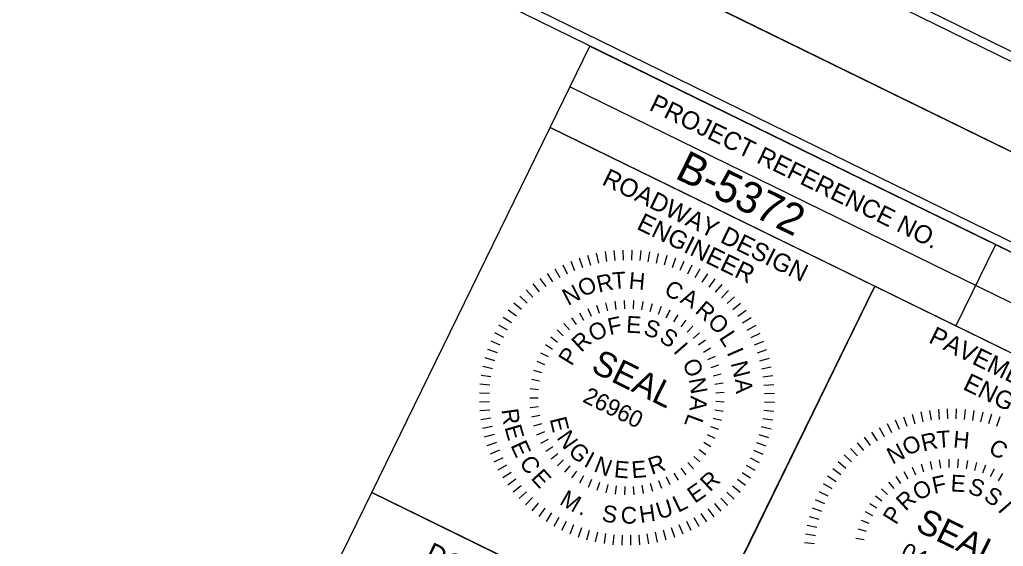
# Model space of a CAD drawing. Extents: x 1518247 to 1523638, y 635234 to 639927.
# Drawn here: x 1522074.1 to 1522346.5, y 638133.1 to 638278.9 of the extents above; entities that cross this region are included whole.
import ezdxf

# ---------------------------------------------------------------- set-up
doc = ezdxf.new("R2010")
doc.units = 0
for name, color, linetype in [('Default', 7, 'Continuous'), ('DTM TIN Hull White', 7, 'Continuous'), ('Prop Dimension Text', 7, 'Continuous'), ('Sheet Cutting Line CELL', 7, 'Continuous'), ('Sheet Plot Border Inside CELL', 7, 'Continuous'), ('Sheet Plot Border Outside CELL', 7, 'Continuous'), ('Sheet Sticker Exception Certification CELL', 7, 'Continuous'), ('Sheet Typical CELL', 7, 'Continuous')]:
    doc.layers.add(name, color=color, linetype=linetype)

msp = doc.modelspace()

# ---------------------------------------------------------------- linework, layer by layer
at = {"layer": 'Default'}
for points in [[(1522438.02, 638198.63), (1520925.25, 638938.49), (1521408.53, 639926.64), (1522921.3, 639186.78)], [(1520441.97, 637950.34), (1521954.73, 637210.48), (1522438.02, 638198.63), (1520925.25, 638938.49)]]:
    msp.add_lwpolyline(points, close=True, dxfattribs=at)
at = {"layer": 'DTM TIN Hull White'}
for p, q in [((1522233.81, 638214.21), (1522234.39, 638211.49)), ((1522236.24, 638214.65), (1522236.65, 638211.9)), ((1522238.69, 638214.94), (1522238.94, 638212.17)), ((1522241.16, 638215.09), (1522241.23, 638212.3)), ((1522243.63, 638215.08), (1522243.53, 638212.29)), ((1522246.09, 638214.93), (1522245.83, 638212.15)), ((1522248.54, 638214.62), (1522248.11, 638211.86)), ((1522250.97, 638214.17), (1522250.38, 638211.45)), ((1522226.74, 638212.03), (1522227.8, 638209.46)), ((1522229.05, 638212.9), (1522229.95, 638210.26)), ((1522231.41, 638213.63), (1522232.15, 638210.94)), ((1522253.37, 638213.57), (1522252.61, 638210.89)), ((1522255.72, 638212.83), (1522254.8, 638210.2)), ((1522258.02, 638211.95), (1522256.95, 638209.38)), ((1522220.18, 638208.61), (1522221.69, 638206.27)), ((1522222.3, 638209.88), (1522223.66, 638207.45)), ((1522224.49, 638211.02), (1522225.7, 638208.52)), ((1522260.28, 638210.93), (1522259.05, 638208.43)), ((1522262.46, 638209.77), (1522261.09, 638207.35)), ((1522264.57, 638208.49), (1522263.05, 638206.16)), ((1522216.2, 638205.69), (1522217.98, 638203.55)), ((1522218.14, 638207.21), (1522219.79, 638204.96)), ((1522266.6, 638207.08), (1522264.94, 638204.85)), ((1522214.34, 638204.06), (1522216.25, 638202.03)), ((1522268.53, 638205.56), (1522266.75, 638203.42)), ((1522270.38, 638203.91), (1522268.47, 638201.89)), ((1522210.95, 638200.48), (1522213.09, 638198.69)), ((1522212.59, 638202.33), (1522214.62, 638200.41)), ((1522236.38, 638200.51), (1522236.89, 638198.24)), ((1522238.95, 638200.96), (1522239.23, 638198.65)), ((1522241.54, 638201.16), (1522241.6, 638198.84)), ((1522244.14, 638201.1), (1522243.98, 638198.79)), ((1522246.73, 638200.8), (1522246.35, 638198.51)), ((1522249.27, 638200.24), (1522248.67, 638198)), ((1522272.12, 638202.16), (1522270.08, 638200.26)), ((1522273.75, 638200.31), (1522271.61, 638198.53)), ((1522209.42, 638198.54), (1522211.66, 638196.88)), ((1522229.11, 638197.73), (1522230.24, 638195.7)), ((1522231.44, 638198.89), (1522232.38, 638196.76)), ((1522233.87, 638199.82), (1522234.6, 638197.61)), ((1522251.75, 638199.45), (1522250.93, 638197.27)), ((1522254.14, 638198.41), (1522253.12, 638196.33)), ((1522253.12, 638196.33), (1522254.14, 638198.41)), ((1522275.27, 638198.36), (1522273.02, 638196.72)), ((1522208.02, 638196.51), (1522210.35, 638194.99)), ((1522224.84, 638194.76), (1522226.34, 638192.99)), ((1522226.91, 638196.35), (1522228.23, 638194.44)), ((1522256.42, 638197.16), (1522255.2, 638195.18)), ((1522258.57, 638195.69), (1522257.17, 638193.84)), ((1522276.67, 638196.33), (1522274.32, 638194.82)), ((1522205.58, 638192.22), (1522208.08, 638190.99)), ((1522206.74, 638194.4), (1522209.16, 638193.03)), ((1522222.94, 638192.98), (1522224.61, 638191.36)), ((1522260.56, 638194.02), (1522258.99, 638192.31)), ((1522262.39, 638192.16), (1522260.66, 638190.61)), ((1522277.94, 638194.21), (1522275.51, 638192.85)), ((1522204.56, 638189.97), (1522207.13, 638188.89)), ((1522221.22, 638191.03), (1522223.04, 638189.58)), ((1522264.02, 638190.13), (1522262.15, 638188.76)), ((1522279.08, 638192.02), (1522276.57, 638190.81)), ((1522280.09, 638189.77), (1522277.51, 638188.71)), ((1522203.68, 638187.66), (1522206.31, 638186.75)), ((1522218.39, 638186.67), (1522220.44, 638185.59)), ((1522219.7, 638188.91), (1522221.64, 638187.65)), ((1522265.46, 638187.96), (1522263.46, 638186.77)), ((1522280.96, 638187.45), (1522278.32, 638186.55)), ((1522202.94, 638185.31), (1522205.62, 638184.55)), ((1522217.3, 638184.3), (1522219.45, 638183.43)), ((1522266.68, 638185.66), (1522264.57, 638184.67)), ((1522281.69, 638185.1), (1522279, 638184.36)), ((1522202.34, 638182.91), (1522205.06, 638182.32)), ((1522216.44, 638181.84), (1522218.67, 638181.19)), ((1522267.66, 638183.25), (1522265.48, 638182.47)), ((1522282.27, 638182.7), (1522279.55, 638182.12)), ((1522201.89, 638180.48), (1522204.64, 638180.05)), ((1522215.83, 638179.31), (1522218.1, 638178.87)), ((1522268.42, 638180.76), (1522266.17, 638180.2)), ((1522282.71, 638180.27), (1522279.96, 638179.86)), ((1522201.58, 638178.04), (1522204.36, 638177.78)), ((1522215.46, 638176.73), (1522217.77, 638176.52)), ((1522268.93, 638178.21), (1522266.63, 638177.86)), ((1522283, 638177.82), (1522280.23, 638177.57)), ((1522201.42, 638173.1), (1522204.21, 638173.18)), ((1522201.43, 638175.57), (1522204.21, 638175.48)), ((1522215.35, 638174.14), (1522217.67, 638174.15)), ((1522269.19, 638175.62), (1522266.87, 638175.49)), ((1522269.2, 638173.01), (1522266.88, 638173.12)), ((1522283.13, 638172.88), (1522280.35, 638172.97)), ((1522283.14, 638175.35), (1522280.36, 638175.27)), ((1522201.56, 638170.63), (1522204.34, 638170.88)), ((1522215.48, 638171.54), (1522217.79, 638171.77)), ((1522268.95, 638170.42), (1522266.65, 638170.75)), ((1522282.98, 638170.42), (1522280.21, 638170.67)), ((1522323.67, 638170.27), (1522324.24, 638167.54)), ((1522326.09, 638170.71), (1522326.51, 638167.95)), ((1522328.55, 638171), (1522328.79, 638168.22)), ((1522331.01, 638171.14), (1522331.09, 638168.35)), ((1522333.48, 638171.13), (1522333.39, 638168.35)), ((1522335.95, 638170.98), (1522335.69, 638168.2)), ((1522338.39, 638170.68), (1522337.97, 638167.92)), ((1522201.86, 638168.18), (1522204.61, 638168.6)), ((1522215.86, 638168.96), (1522218.14, 638169.41)), ((1522268.46, 638167.87), (1522266.21, 638168.42)), ((1522282.68, 638167.97), (1522279.92, 638168.4)), ((1522316.6, 638168.09), (1522317.66, 638165.51)), ((1522318.91, 638168.95), (1522319.81, 638166.32)), ((1522321.27, 638169.68), (1522322.01, 638167)), ((1522340.83, 638170.22), (1522340.23, 638167.5)), ((1522343.22, 638169.63), (1522342.46, 638166.94)), ((1522345.57, 638168.88), (1522344.66, 638166.25)), ((1522202.3, 638165.76), (1522205.02, 638166.33)), ((1522216.5, 638166.44), (1522218.71, 638167.11)), ((1522217.36, 638163.98), (1522219.51, 638164.87)), ((1522267.73, 638165.37), (1522265.54, 638166.13)), ((1522282.23, 638165.54), (1522279.5, 638166.13)), ((1522312.15, 638165.94), (1522313.51, 638163.51)), ((1522314.34, 638167.08), (1522315.55, 638164.57)), ((1522202.88, 638163.35), (1522205.57, 638164.1)), ((1522218.47, 638161.63), (1522220.52, 638162.71)), ((1522266.75, 638162.95), (1522264.64, 638163.92)), ((1522281.63, 638163.14), (1522278.95, 638163.9)), ((1522308, 638163.27), (1522309.65, 638161.02)), ((1522310.04, 638164.67), (1522311.54, 638162.32)), ((1522203.61, 638161), (1522206.24, 638161.9)), ((1522204.48, 638158.69), (1522207.05, 638159.74)), ((1522219.8, 638159.39), (1522221.74, 638160.67)), ((1522262.3, 638159.89), (1522264.18, 638158.53)), ((1522265.55, 638160.65), (1522263.55, 638161.81)), ((1522280, 638158.48), (1522277.44, 638159.56)), ((1522280.89, 638160.79), (1522278.26, 638161.71)), ((1522304.2, 638160.12), (1522306.1, 638158.08)), ((1522306.05, 638161.75), (1522307.83, 638159.61)), ((1522205.49, 638156.43), (1522207.99, 638157.64)), ((1522221.34, 638157.29), (1522223.14, 638158.75)), ((1522223.07, 638155.34), (1522224.73, 638156.97)), ((1522262.51, 638156.43), (1522260.77, 638157.96)), ((1522278.99, 638156.23), (1522276.48, 638157.46)), ((1522302.45, 638158.38), (1522304.48, 638156.46)), ((1522328.8, 638157.01), (1522329.09, 638154.71)), ((1522331.4, 638157.21), (1522331.46, 638154.89)), ((1522334, 638157.16), (1522333.84, 638154.84)), ((1522336.59, 638156.85), (1522336.2, 638154.56)), ((1522206.63, 638154.24), (1522209.06, 638155.6)), ((1522226.46, 638155.37), (1522224.97, 638153.59)), ((1522227.06, 638152), (1522228.37, 638153.92)), ((1522258.71, 638152.88), (1522257.3, 638154.72)), ((1522260.69, 638154.56), (1522259.11, 638156.25)), ((1522277.83, 638154.05), (1522275.41, 638155.42)), ((1522299.28, 638154.59), (1522301.52, 638152.94)), ((1522300.8, 638156.53), (1522302.94, 638154.75)), ((1522321.3, 638154.94), (1522322.23, 638152.82)), ((1522323.73, 638155.87), (1522324.45, 638153.66)), ((1522326.23, 638156.57), (1522326.74, 638154.3)), ((1522339.13, 638156.3), (1522338.52, 638154.06)), ((1522341.6, 638155.5), (1522340.79, 638153.33)), ((1522344, 638154.47), (1522342.97, 638152.39)), ((1522342.97, 638152.39), (1522344, 638154.47)), ((1522207.9, 638152.13), (1522210.24, 638153.63)), ((1522209.29, 638150.09), (1522211.54, 638151.73)), ((1522229.27, 638150.64), (1522230.39, 638152.67)), ((1522231.61, 638149.49), (1522232.53, 638151.62)), ((1522251.92, 638149.07), (1522251.09, 638151.23)), ((1522254.3, 638150.11), (1522253.27, 638152.19)), ((1522256.58, 638151.39), (1522255.34, 638153.35)), ((1522275.14, 638149.91), (1522272.9, 638151.57)), ((1522276.55, 638151.94), (1522274.21, 638153.46)), ((1522297.87, 638152.56), (1522300.21, 638151.05)), ((1522316.76, 638152.4), (1522318.08, 638150.49)), ((1522318.97, 638153.78), (1522320.1, 638151.75)), ((1522346.28, 638153.21), (1522345.06, 638151.24)), ((1522210.82, 638148.14), (1522212.96, 638149.92)), ((1522234.04, 638148.58), (1522234.75, 638150.79)), ((1522236.56, 638147.9), (1522237.05, 638150.17)), ((1522239.12, 638147.47), (1522239.4, 638149.78)), ((1522241.72, 638147.29), (1522241.77, 638149.62)), ((1522244.33, 638147.36), (1522244.15, 638149.68)), ((1522246.91, 638147.69), (1522246.51, 638149.97)), ((1522249.45, 638148.26), (1522248.83, 638150.49)), ((1522273.62, 638147.97), (1522271.48, 638149.76)), ((1522296.59, 638150.46), (1522299.01, 638149.08)), ((1522312.8, 638149.03), (1522314.47, 638147.42)), ((1522314.69, 638150.81), (1522316.2, 638149.04)), ((1522212.44, 638146.29), (1522214.48, 638148.19)), ((1522214.18, 638144.54), (1522216.1, 638146.56)), ((1522270.22, 638144.39), (1522268.32, 638146.42)), ((1522271.97, 638146.13), (1522269.94, 638148.04)), ((1522294.42, 638146.02), (1522296.99, 638144.95)), ((1522295.44, 638148.27), (1522297.94, 638147.05)), ((1522311.08, 638147.08), (1522312.89, 638145.63)), ((1522216.03, 638142.89), (1522217.82, 638145.03)), ((1522217.97, 638141.37), (1522219.62, 638143.61)), ((1522266.42, 638141.24), (1522264.77, 638143.49)), ((1522268.37, 638142.76), (1522266.59, 638144.9)), ((1522293.54, 638143.72), (1522296.16, 638142.8)), ((1522309.55, 638144.97), (1522311.5, 638143.71)), ((1522220, 638139.96), (1522221.51, 638142.3)), ((1522222.11, 638138.68), (1522223.48, 638141.1)), ((1522262.27, 638138.57), (1522260.91, 638141)), ((1522264.38, 638139.84), (1522262.88, 638142.18)), ((1522292.79, 638141.36), (1522295.47, 638140.61)), ((1522307.15, 638140.36), (1522309.3, 638139.49)), ((1522308.24, 638142.72), (1522310.3, 638141.65)), ((1522224.29, 638137.52), (1522225.52, 638140.03)), ((1522226.54, 638136.5), (1522227.61, 638139.07)), ((1522228.85, 638135.62), (1522229.76, 638138.25)), ((1522231.2, 638134.88), (1522231.96, 638137.56)), ((1522255.51, 638135.55), (1522254.61, 638138.19)), ((1522257.82, 638136.42), (1522256.76, 638139)), ((1522260.08, 638137.43), (1522258.87, 638139.93)), ((1522292.2, 638138.97), (1522294.92, 638138.37)), ((1522306.3, 638137.9), (1522308.52, 638137.24)), ((1522233.59, 638134.28), (1522234.19, 638137)), ((1522236.03, 638133.83), (1522236.45, 638136.59)), ((1522238.47, 638133.53), (1522238.73, 638136.3)), ((1522240.94, 638133.38), (1522241.03, 638136.16)), ((1522243.41, 638133.36), (1522243.33, 638136.15)), ((1522245.87, 638133.51), (1522245.63, 638136.28)), ((1522248.33, 638133.8), (1522247.91, 638136.55)), ((1522250.75, 638134.24), (1522250.18, 638136.96)), ((1522253.16, 638134.82), (1522252.41, 638137.51)), ((1522291.74, 638136.54), (1522294.5, 638136.11)), ((1522305.68, 638135.37), (1522307.96, 638134.93)), ((1522291.44, 638134.09), (1522294.21, 638133.83))]:
    msp.add_line(p, q, dxfattribs=at)
at = {"layer": 'Sheet Cutting Line CELL'}
for p, q in [((1520925.25, 638938.49), (1522438.02, 638198.63)), ((1522438.02, 638198.63), (1520925.25, 638938.49))]:
    msp.add_line(p, q, dxfattribs=at)
at = {"layer": 'Sheet Plot Border Inside CELL'}
for points in [[(1522907.39, 639168.59), (1521410.35, 639900.76), (1520946.79, 638952.95), (1522443.84, 638220.77)], [(1522424.11, 638180.44), (1520927.06, 638912.61), (1520463.51, 637964.8), (1521960.55, 637232.62)]]:
    msp.add_lwpolyline(points, close=True, dxfattribs=at)
at = {"layer": 'Sheet Plot Border Outside CELL'}
for points in [[(1522921.3, 639186.78), (1521408.53, 639926.64), (1520925.25, 638938.49), (1522438.02, 638198.63)], [(1522438.02, 638198.63), (1520925.25, 638938.49), (1520441.97, 637950.34), (1521954.73, 637210.48)]]:
    msp.add_lwpolyline(points, close=True, dxfattribs=at)
at = {"layer": 'Sheet Sticker Exception Certification CELL'}
for p, q in [((1522161.3, 638126.86), (1522171.62, 638147.97)), ((1522171.62, 638147.97), (1522351.32, 638060.08))]:
    msp.add_line(p, q, dxfattribs=at)
at = {"layer": 'Sheet Typical CELL'}
for p, q in [((1522226.54, 638260.26), (1522406.25, 638172.37)), ((1522344.36, 638216.55), (1522333.38, 638194.09)), ((1522310.92, 638205.07), (1522261.52, 638104.06))]:
    msp.add_line(p, q, dxfattribs=at)
for points in [[(1522895.04, 639171.79), (1521547.57, 639830.81), (1521086.25, 638887.58), (1522433.73, 638228.56)], [(1522411.76, 638183.64), (1521064.29, 638842.66), (1520602.97, 637899.43), (1521950.45, 637240.41)], [(1522232.05, 638271.53), (1522411.76, 638183.64), (1522400.76, 638161.14), (1522221.05, 638249.03)], [(1522221.05, 638249.03), (1522310.92, 638205.07), (1522261.5, 638104.01), (1522171.62, 638147.97)], [(1522310.92, 638205.07), (1522400.76, 638161.14), (1522351.33, 638060.08), (1522261.5, 638104.01)]]:
    msp.add_lwpolyline(points, close=True, dxfattribs=at)

# ---------------------------------------------------------------- texts
at = {"layer": 'DTM TIN Hull White'}
for s, height, rotation, p in [('R', 4.64, 12.5453, (1522234.47, 638203.27)), ('T', 4.64, 4.3843, (1522238.41, 638204.23)), ('H', 4.64, 354.9524, (1522242.66, 638204.4)), ('O', 4.64, 25.602, (1522230.07, 638201.94)), ('C', 4.64, 331.2417, (1522252.26, 638203.01)), ('N', 4.64, 27.5614, (1522225.96, 638199.6)), ('A', 4.64, 331.2417, (1522256.77, 638200.7)), ('R', 4.64, 319.2324, (1522260.88, 638197.92)), ('O', 4.64, 27.4216, (1522233.09, 638189.51)), ('F', 4.64, 12.1253, (1522237.51, 638191.52)), ('E', 4.64, 356.8291, (1522242, 638192.24)), ('S', 4.64, 341.5328, (1522246.61, 638191.75)), ('O', 4.64, 316.1756, (1522264.33, 638194.74)), ('R', 4.64, 42.7178, (1522229.61, 638186.58)), ('S', 4.64, 326.2366, (1522250.94, 638190.06)), ('L', 4.64, 303.0393, (1522267.66, 638190.81)), ('I', 4.64, 310.9403, (1522254.93, 638186.99)), ('P', 4.64, 58.0141, (1522226.95, 638182.76)), ('SEAL', 6.965, 333.8847, (1522232, 638181.6)), ('I', 4.64, 293.4638, (1522269.84, 638186.74)), ('O', 4.64, 295.6441, (1522257.49, 638183.72)), ('N', 4.64, 284.1693, (1522270.96, 638183.75)), ('N', 4.64, 280.3478, (1522259.34, 638179.35)), ('A', 4.64, 274.4018, (1522272.2, 638179.33)), ('26960', 4.64, 333.8847, (1522229.75, 638173.19)), ('A', 4.64, 265.0516, (1522259.95, 638174.82)), ('R', 4.64, 277.8197, (1522207.53, 638170.9)), ('E', 4.64, 283.9548, (1522220.86, 638168.31)), ('L', 4.64, 249.7554, (1522259.28, 638170.04)), ('E', 4.64, 285.8915, (1522208.35, 638166.03)), ('N', 4.64, 304.8099, (1522222.66, 638163.13)), ('T', 4.64, 4.3843, (1522328.27, 638160.28)), ('H', 4.64, 354.9524, (1522332.51, 638160.45)), ('E', 4.64, 294.5343, (1522209.97, 638161.03)), ('O', 4.64, 25.602, (1522319.93, 638158)), ('R', 4.64, 12.5453, (1522324.32, 638159.32)), ('C', 4.64, 331.2417, (1522342.11, 638159.06)), ('G', 4.64, 313.5761, (1522225.78, 638159.17)), ('N', 4.64, 27.5614, (1522315.81, 638155.65)), ('C', 4.64, 303.2069, (1522212.32, 638156.32)), ('I', 4.64, 331.6709, (1522230.09, 638155.41)), ('N', 4.64, 339.3006, (1522232.85, 638153.88)), ('E', 4.64, 354.6926, (1522238.58, 638152.22)), ('E', 4.64, 4.6785, (1522243.73, 638151.91)), ('R', 4.64, 18.4496, (1522249.12, 638152.87)), ('E', 4.64, 312.1794, (1522215.49, 638151.85)), ('R', 4.64, 43.5571, (1522265.28, 638147.97)), ('F', 4.64, 12.1253, (1522327.36, 638147.57)), ('E', 4.64, 356.8291, (1522331.85, 638148.29)), ('S', 4.64, 341.5328, (1522336.47, 638147.81)), ('M', 4.64, 329.9747, (1522223.34, 638144.89)), ('E', 4.64, 34.8844, (1522261.08, 638144.82)), ('O', 4.64, 27.4216, (1522322.94, 638145.57)), ('S', 4.64, 326.2366, (1522340.8, 638146.11)), ('U', 4.64, 17.2091, (1522251.2, 638140.48)), ('L', 4.64, 26.0918, (1522256.44, 638142.33)), ('R', 4.64, 42.7178, (1522319.46, 638142.64)), ('S', 4.64, 350.5013, (1522235.12, 638140.07)), ('C', 4.64, 359.5039, (1522240.56, 638139.37)), ('H', 4.64, 8.3265, (1522246.03, 638139.53)), ('P', 4.64, 58.0141, (1522316.81, 638138.81)), ('SEAL', 6.965, 333.8847, (1522321.85, 638137.65)), ('I', 4.64, 310.9403, (1522344.79, 638143.04)), ('.', 4.64, 337.717, (1522228.72, 638142.1)), ('044590', 4.64, 333.8847, (1522317.77, 638130.14))]:
    msp.add_text(s, height=height, rotation=rotation, dxfattribs=at).set_placement(p)
at = {"layer": 'Prop Dimension Text'}
msp.add_text('B-5372', height=8.643, rotation=333.8962, dxfattribs=at).set_placement((1522255.3, 638235.13))
at = {"layer": 'Sheet Sticker Exception Certification CELL'}
msp.add_text('DOCUMENT NOT CONSIDERED FINAL', height=5.5, rotation=333.9377, dxfattribs=at).set_placement((1522186, 638129.42))
at = {"layer": 'Sheet Typical CELL'}
for s, height, p in [('PROJECT REFERENCE NO.', 5.0001, (1522248.17, 638253.96)), ('ROADWAY DESIGN', 5.0001, (1522235.09, 638233.37)), ('ENGINEER', 5, (1522244.7, 638221.04)), ('PAVEMENT DESIGN', 5.0001, (1522325.57, 638189.61)), ('ENGINEER', 5, (1522335.05, 638176.68))]:
    msp.add_text(s, height=height, rotation=333.9377, dxfattribs=at).set_placement(p)

doc.saveas('drawing.dxf')
